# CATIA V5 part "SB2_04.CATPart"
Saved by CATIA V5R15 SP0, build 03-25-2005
Part number: SB2_04.1
Material "Green Blue": density 7860 kg/m3, Young's modulus 2e+11 Pa, Poisson ratio 0.266
Bounding box of the stored display mesh (mm): x -158 to 0, y 0 to 316, z 0 to 47
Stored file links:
  E:\#01 CATIA Lecture Materials\#06 DMU\#11 DMU Page01 KIN EX11\SB2_04.CATPart
  C:\Documents and Settings\c-cap\My Documents\정욱순\레고\SB2-16.CATPart
  E:\공학과제\SB2_04_02.CATPart
  C:\Program Files\Dassault Systemes\B20\win_b64\startup\materials\Catalog.CATMaterial
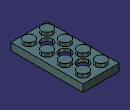
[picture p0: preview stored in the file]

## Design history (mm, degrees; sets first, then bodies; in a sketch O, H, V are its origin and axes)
Body1 (main body), material "Green Blue"
  Sketch1 on zx-plane, origin (0, 0, 0), H (-1, 0, 0), V (0, 0, 1)
    point P1 (0, 32)
    line L1 (0, 32) -> (158, 32)
    line L2 (158, 32) -> (158, 0)
    line L3 (158, 0) -> (0, 0)
    line L4 (0, 0) -> (0, 32)
    point P3 (158, 0)
    distance L2 L4 = 158
    length L2 = 32
    coincidence: P1 V, P3 H
    horizontal: L1 H, L3 H
    vertical: L2 V, L4 V
  Pad1: profile Sketch1, direction (0, 1, 0), length 316
  Sketch2 on xy-plane, origin (0, 0, 0), H (1, 0, 0), V (0, 1, 0)
    circle A1 centre (-39.5, 39.5) radius 23.5
    point P1 (-39.5, 39.5)
    reference projected line E1 (0, 0) -> (0, 316) from edge [face of Pad1 from Sketch1.L4 | face of Pad1 from Sketch1.L1]
    reference projected line E2 (-158, 0) -> (0, 0) from edge [start face of Pad1 | face of Pad1 from Sketch1.L1]
    radius A1 = 23.5
    distance P1 E1 = 39.5
    distance P1 E2 = 39.5
  Pad2: profile Sketch2, direction (0, 0, 1), length 47
  RectPattern1: of Pad2, direction 1 instances 2, spacing 79, along xy-plane reversed, direction 2 instances 4, spacing 79, along xy-plane
  Shell1: ExtOffset 0, Face face of Pad2, IntOffset 15
  Sketch3 on face of Pad1 from Sketch1.L1, origin (0, 0, 32), H (1, 0, 0), V (0, 1, 0)
    circle A1 centre (-79, 79) radius 24.5
    point P1 (-79, 79)
    reference projected point E1 (-39.5, 118.5) from axis of face of RectPattern1
    reference projected point E2 (-39.5, 39.5) from axis of face of Pad2 from Sketch2.A1
    reference projected point E3 (-39.5, 118.5) from axis of face of RectPattern1
    reference projected point E4 (-118.5, 118.5) from axis of face of RectPattern1
    radius A1 = 24.5
    equidistance: E1 E2 P1, E3 E4 P1
  Pocket1: profile Sketch3, direction (0, 0, -1), length 20
  RectPattern2: of Pocket1, direction 1 instances 3, spacing 79, along edge [face of Pad1 from Sketch1.L4 | face of Pad1 from Sketch1.L1], direction 2 instances 4, spacing 79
